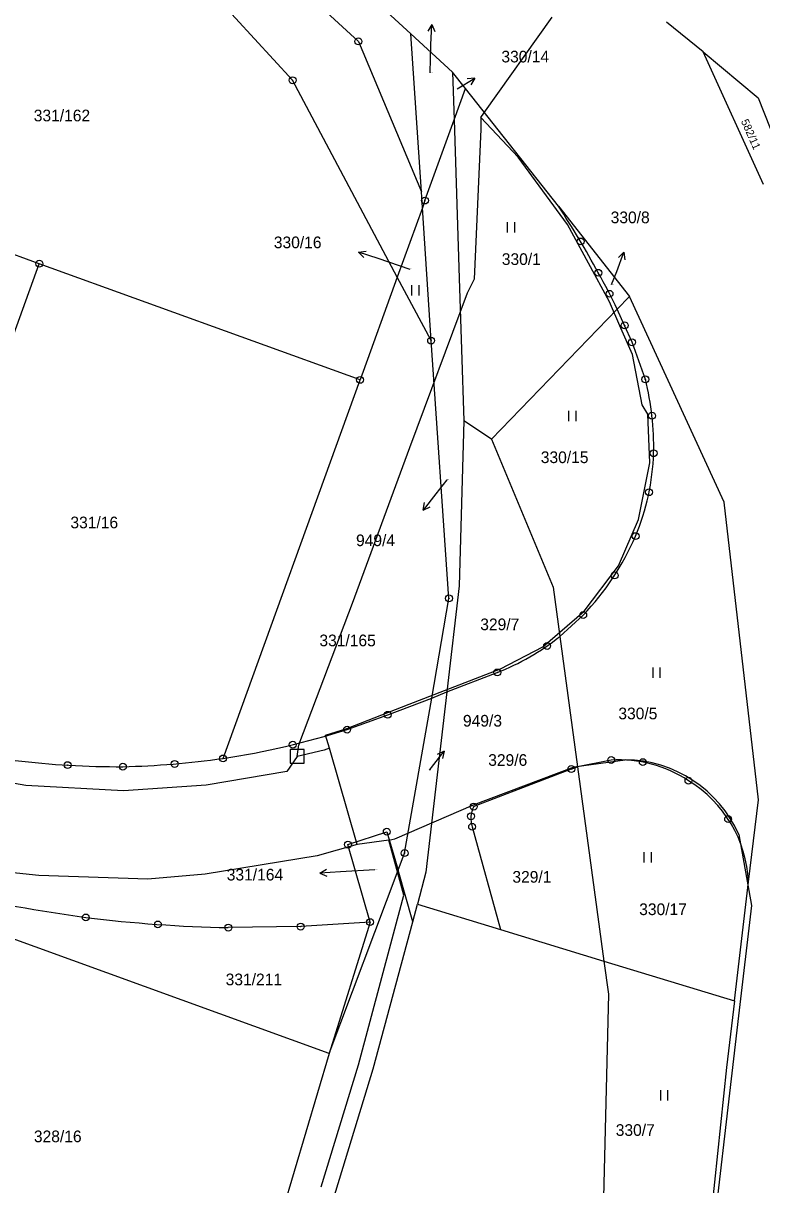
# Model space of a CAD drawing. Extents: x -770973 to -770265, y -1049936 to -1049427.
# Drawn here: x -770575 to -770521.2, y -1049731.9 to -1049647.3 of the extents above; entities that cross this region are included whole.
import ezdxf

# ---------------------------------------------------------------- set-up
doc = ezdxf.new("R2010")
doc.units = 0
for name, color, linetype in [('Vrstva 1', 7, 'Continuous'), ('Vrstva 13', 7, 'Continuous'), ('Vrstva 14', 7, 'Continuous'), ('Vrstva 16', 7, 'Continuous'), ('Vrstva 23', 7, 'Continuous'), ('Vrstva 28', 7, 'Continuous'), ('Vrstva 50', 7, 'Continuous')]:
    doc.layers.add(name, color=color, linetype=linetype)

msp = doc.modelspace()

# ---------------------------------------------------------------- linework, layer by layer
at = {"layer": 'Vrstva 1'}
for p, q in [((-770546.73, -1049648.09), (-770562.36, -1049633.74)), ((-770564.3, -1049636.03), (-770550.56, -1049648.64)), ((-770555.35, -1049651.47), (-770568.56, -1049637.05)), ((-770525.45, -1049649.4), (-770528.12, -1049647.23)), ((-770550.56, -1049648.64), (-770545.97, -1049659.6)), ((-770545.97, -1049659.6), (-770546.73, -1049648.09)), ((-770543.7, -1049650.87), (-770546.73, -1049648.09)), ((-770521.04, -1049659.06), (-770525.45, -1049649.4)), ((-770525.45, -1049649.4), (-770521.43, -1049652.75)), ((-770543.7, -1049650.87), (-770543.59, -1049654.36)), ((-770542.75, -1049652.07), (-770543.7, -1049650.87)), ((-770547.73, -1049665.8), (-770555.35, -1049651.47)), ((-770543.59, -1049654.36), (-770542.75, -1049652.07)), ((-770535.99, -1049660.64), (-770542.75, -1049652.07)), ((-770521.43, -1049652.75), (-770517.95, -1049661.6)), ((-770545.71, -1049660.23), (-770543.59, -1049654.36)), ((-770543.59, -1049654.36), (-770543.21, -1049665.87)), ((-770545.9, -1049660.75), (-770545.97, -1049659.6)), ((-770573.81, -1049664.83), (-770587.12, -1049660.01)), ((-770545.71, -1049660.23), (-770545.9, -1049660.75)), ((-770535.99, -1049660.64), (-770530.8, -1049667.22)), ((-770545.9, -1049660.75), (-770547.73, -1049665.8)), ((-770545.26, -1049670.43), (-770545.9, -1049660.75)), ((-770585.68, -1049697.62), (-770573.81, -1049664.83)), ((-770550.44, -1049673.29), (-770573.81, -1049664.83)), ((-770547.73, -1049665.8), (-770550.44, -1049673.29)), ((-770545.26, -1049670.43), (-770547.73, -1049665.8)), ((-770543.21, -1049665.87), (-770542.87, -1049676.27)), ((-770530.8, -1049667.22), (-770531.7, -1049668.15)), ((-770523.91, -1049682.19), (-770530.8, -1049667.22)), ((-770531.7, -1049668.15), (-770540.87, -1049677.61)), ((-770531.16, -1049669.32), (-770531.7, -1049668.15)), ((-770530.62, -1049670.55), (-770531.16, -1049669.32)), ((-770543.96, -1049689.2), (-770545.26, -1049670.43)), ((-770529.65, -1049673.25), (-770530.62, -1049670.55)), ((-770560.42, -1049700.86), (-770550.44, -1049673.29)), ((-770542.87, -1049676.27), (-770543.21, -1049688.3)), ((-770540.87, -1049677.61), (-770542.87, -1049676.27)), ((-770540.87, -1049677.61), (-770536.38, -1049688.39)), ((-770521.42, -1049703.88), (-770523.91, -1049682.19)), ((-770543.21, -1049688.3), (-770544.11, -1049696.02)), ((-770536.38, -1049688.39), (-770535.89, -1049691.98)), ((-770545.22, -1049696.46), (-770543.96, -1049689.2)), ((-770534.18, -1049690.42), (-770535.89, -1049691.98)), ((-770535.89, -1049691.98), (-770534.6, -1049701.47)), ((-770544.11, -1049696.02), (-770540.44, -1049694.6)), ((-770544.11, -1049696.02), (-770545.64, -1049709.14)), ((-770545.22, -1049696.46), (-770544.11, -1049696.02)), ((-770548.42, -1049697.68), (-770545.22, -1049696.46)), ((-770547.19, -1049707.75), (-770545.22, -1049696.46)), ((-770551.38, -1049698.76), (-770548.42, -1049697.68)), ((-770532.14, -1049700.98), (-770534.6, -1049701.47)), ((-770535.05, -1049701.63), (-770542.16, -1049704.37)), ((-770535.05, -1049701.63), (-770534.6, -1049701.47)), ((-770534.6, -1049701.47), (-770532.67, -1049715.62)), ((-770522.13, -1049709.84), (-770521.42, -1049703.88)), ((-770551.32, -1049707.14), (-770548.49, -1049706.2)), ((-770548.49, -1049706.2), (-770547.66, -1049709)), ((-770542.27, -1049705.84), (-770540.21, -1049713.32)), ((-770549.71, -1049712.78), (-770551.32, -1049707.14)), ((-770547.66, -1049709), (-770547.19, -1049707.75)), ((-770552.69, -1049722.34), (-770547.66, -1049709)), ((-770546.6, -1049712.76), (-770547.66, -1049709)), ((-770545.64, -1049709.14), (-770546.25, -1049711.47)), ((-770523.16, -1049718.52), (-770522.13, -1049709.84)), ((-770552.69, -1049722.34), (-770583.79, -1049711.08)), ((-770546.6, -1049712.76), (-770546.25, -1049711.47)), ((-770546.25, -1049711.47), (-770540.21, -1049713.32)), ((-770554.76, -1049713.11), (-770560.04, -1049713.18)), ((-770549.71, -1049712.78), (-770554.76, -1049713.11)), ((-770549.71, -1049712.78), (-770552.69, -1049722.34)), ((-770549.48, -1049723.46), (-770546.6, -1049712.76)), ((-770540.21, -1049713.32), (-770532.67, -1049715.62)), ((-770532.67, -1049715.62), (-770532.33, -1049718.02)), ((-770532.67, -1049715.62), (-770523.16, -1049718.52)), ((-770532.33, -1049718.02), (-770532.95, -1049742.96)), ((-770523.16, -1049718.52), (-770523.73, -1049723.36)), ((-770552.69, -1049722.34), (-770559.02, -1049743.61)), ((-770556.01, -1049744.77), (-770549.48, -1049723.46)), ((-770523.73, -1049723.36), (-770525, -1049735.43))]:
    msp.add_line(p, q, dxfattribs=at)
for centre, radius, start, end in [((-770585.493, -1049693.64), 59.494, 28.23919, 33.68832), ((-770574.083, -1049688.45), 46.994, 25.59304, 29.24725), ((-770549.116, -1049678.144), 20.072, 358.61365, 14.11348), ((-770546.161, -1049678.081), 17.12, 337.36347, 358.16211), ((-770548.173, -1049676.98), 19.402, 316.15437, 336.64965), ((-770546.558, -1049678.714), 17.023, 291.06318, 308.80557), ((-770569.584, -1049640.903), 60.653, 278.69011, 287.46571), ((-770568.043, -1049639.768), 61.693, 262.99237, 270.30037), ((-770569.078, -1049640.229), 61.246, 271.27053, 278.12682), ((-770531.588, -1049710.224), 9.26, 56.74475, 93.41775), ((-770531.296, -1049710.312), 9.179, 2.94609, 58.56839), ((-770540.45, -1049705.237), 1.917, 153.10848, 198.33259), ((-770552.252, -1049582.755), 130.951, 257.55595, 262.02506), ((-770558.126, -1049613.159), 100.039, 262.94086, 268.9036)]:
    msp.add_arc(centre, radius, start, end, dxfattribs=at)
at = {"layer": 'Vrstva 13'}
for p, q in [((-770545.33, -1049650.93), (-770545.27, -1049648.9)), ((-770546.78, -1049665.24), (-770549.13, -1049664.46)), ((-770532.11, -1049666.35), (-770531.74, -1049665.39)), ((-770544.11, -1049680.57), (-770544.92, -1049681.6)), ((-770545.39, -1049701.72), (-770545.23, -1049701.51)), ((-770549.36, -1049708.97), (-770551.87, -1049709.12))]:
    msp.add_line(p, q, dxfattribs=at)
at = {"layer": 'Vrstva 16'}
for p, q in [((-770545.22, -1049647.4), (-770545.49, -1049647.89)), ((-770545.27, -1049648.9), (-770545.22, -1049647.4)), ((-770545.22, -1049647.4), (-770544.99, -1049647.91)), ((-770543.36, -1049652.09), (-770542.07, -1049651.32)), ((-770542.07, -1049651.32), (-770542.63, -1049651.36)), ((-770542.07, -1049651.32), (-770542.37, -1049651.79)), ((-770550.55, -1049663.99), (-770550, -1049663.91)), ((-770549.13, -1049664.46), (-770550.55, -1049663.99)), ((-770550.55, -1049663.99), (-770550.16, -1049664.38)), ((-770531.74, -1049665.39), (-770531.21, -1049663.99)), ((-770531.21, -1049663.99), (-770531.62, -1049664.37)), ((-770531.21, -1049663.99), (-770531.15, -1049664.54)), ((-770544.92, -1049681.6), (-770545.85, -1049682.78)), ((-770545.85, -1049682.78), (-770545.74, -1049682.23)), ((-770545.85, -1049682.78), (-770545.34, -1049682.54)), ((-770545.23, -1049701.51), (-770544.31, -1049700.32)), ((-770544.31, -1049700.32), (-770544.82, -1049700.57)), ((-770544.31, -1049700.32), (-770544.42, -1049700.87)), ((-770553.37, -1049709.21), (-770552.88, -1049708.93)), ((-770551.87, -1049709.12), (-770553.37, -1049709.21)), ((-770553.37, -1049709.21), (-770552.85, -1049709.43))]:
    msp.add_line(p, q, dxfattribs=at)
at = {"layer": 'Vrstva 23'}
for p, q in [((-770539.69, -1049662.56), (-770539.69, -1049661.81)), ((-770539.19, -1049661.81), (-770539.19, -1049662.56)), ((-770546.66, -1049667.14), (-770546.66, -1049666.39)), ((-770546.16, -1049666.39), (-770546.16, -1049667.14)), ((-770535.22, -1049676.3), (-770535.22, -1049675.55)), ((-770534.72, -1049675.55), (-770534.72, -1049676.3)), ((-770529.09, -1049694.99), (-770529.09, -1049694.24)), ((-770528.59, -1049694.24), (-770528.59, -1049694.99)), ((-770529.73, -1049708.44), (-770529.73, -1049707.69)), ((-770529.23, -1049707.69), (-770529.23, -1049708.44)), ((-770528.53, -1049725.77), (-770528.53, -1049725.02)), ((-770528.03, -1049725.02), (-770528.03, -1049725.77))]:
    msp.add_line(p, q, dxfattribs=at)
at = {"layer": 'Vrstva 28'}
for centre, radius in [((-770550.56, -1049648.64), 0.25), ((-770550.56, -1049648.64), 0.005), ((-770555.35, -1049651.47), 0.25), ((-770555.35, -1049651.47), 0.005), ((-770545.71, -1049660.23), 0.25), ((-770545.71, -1049660.23), 0.005), ((-770534.37, -1049663.21), 0.25), ((-770534.37, -1049663.21), 0.005), ((-770573.81, -1049664.83), 0.25), ((-770573.81, -1049664.83), 0.005), ((-770533.08, -1049665.49), 0.25), ((-770533.08, -1049665.49), 0.005), ((-770532.26, -1049667.02), 0.25), ((-770532.26, -1049667.02), 0.005), ((-770531.16, -1049669.32), 0.25), ((-770531.16, -1049669.32), 0.005), ((-770545.26, -1049670.43), 0.25), ((-770545.26, -1049670.43), 0.005), ((-770530.62, -1049670.55), 0.25), ((-770530.62, -1049670.55), 0.005), ((-770550.44, -1049673.29), 0.25), ((-770550.44, -1049673.29), 0.005), ((-770529.65, -1049673.25), 0.25), ((-770529.65, -1049673.25), 0.005), ((-770529.17, -1049675.9), 0.25), ((-770529.17, -1049675.9), 0.005), ((-770529.05, -1049678.63), 0.25), ((-770529.05, -1049678.63), 0.005), ((-770529.38, -1049681.47), 0.25), ((-770529.38, -1049681.47), 0.005), ((-770530.36, -1049684.67), 0.25), ((-770530.36, -1049684.67), 0.005), ((-770531.89, -1049687.53), 0.25), ((-770531.89, -1049687.53), 0.005), ((-770543.96, -1049689.2), 0.25), ((-770543.96, -1049689.2), 0.005), ((-770534.18, -1049690.42), 0.25), ((-770534.18, -1049690.42), 0.005), ((-770536.81, -1049692.67), 0.25), ((-770536.81, -1049692.67), 0.005), ((-770540.44, -1049694.6), 0.25), ((-770540.44, -1049694.6), 0.005), ((-770548.42, -1049697.68), 0.25), ((-770548.42, -1049697.68), 0.005), ((-770551.38, -1049698.76), 0.25), ((-770551.38, -1049698.76), 0.005), ((-770555.34, -1049699.86), 0.25), ((-770555.34, -1049699.86), 0.005), ((-770571.74, -1049701.35), 0.25), ((-770567.72, -1049701.46), 0.25), ((-770563.95, -1049701.26), 0.25), ((-770563.95, -1049701.26), 0.005), ((-770560.42, -1049700.86), 0.25), ((-770560.42, -1049700.86), 0.005), ((-770532.14, -1049700.98), 0.25), ((-770532.14, -1049700.98), 0.005), ((-770529.84, -1049701.13), 0.25), ((-770529.84, -1049701.13), 0.005), ((-770571.74, -1049701.35), 0.005), ((-770567.72, -1049701.46), 0.005), ((-770535.05, -1049701.63), 0.25), ((-770535.05, -1049701.63), 0.005), ((-770526.51, -1049702.48), 0.25), ((-770526.51, -1049702.48), 0.005), ((-770542.16, -1049704.37), 0.25), ((-770542.16, -1049704.37), 0.005), ((-770542.36, -1049705.07), 0.25), ((-770542.36, -1049705.07), 0.005), ((-770523.62, -1049705.28), 0.25), ((-770523.62, -1049705.28), 0.005), ((-770548.49, -1049706.2), 0.25), ((-770548.49, -1049706.2), 0.005), ((-770542.27, -1049705.84), 0.25), ((-770542.27, -1049705.84), 0.005), ((-770551.32, -1049707.14), 0.25), ((-770551.32, -1049707.14), 0.005), ((-770547.19, -1049707.75), 0.25), ((-770547.19, -1049707.75), 0.005), ((-770570.42, -1049712.44), 0.25), ((-770570.42, -1049712.44), 0.005), ((-770565.17, -1049712.95), 0.25), ((-770565.17, -1049712.95), 0.005), ((-770560.04, -1049713.18), 0.25), ((-770554.76, -1049713.11), 0.25), ((-770554.76, -1049713.11), 0.005), ((-770549.71, -1049712.78), 0.25), ((-770549.71, -1049712.78), 0.005), ((-770560.04, -1049713.18), 0.005)]:
    msp.add_circle(centre, radius, dxfattribs=at)
at = {"layer": 'Vrstva 50'}
for p, q in [((-770541.42, -1049653.87), (-770536.43, -1049646.88)), ((-770541.64, -1049654.17), (-770541.42, -1049653.87)), ((-770541.64, -1049654.17), (-770541.65, -1049655.02)), ((-770538.91, -1049657.08), (-770541.64, -1049654.17)), ((-770541.65, -1049655.02), (-770542.12, -1049665.95)), ((-770535.32, -1049661.98), (-770538.91, -1049657.08)), ((-770532.27, -1049667.61), (-770535.32, -1049661.98)), ((-770542.12, -1049665.95), (-770542.64, -1049666.97)), ((-770542.64, -1049666.97), (-770546.84, -1049678.24)), ((-770531.44, -1049669.52), (-770532.27, -1049667.61)), ((-770530.59, -1049671.43), (-770531.44, -1049669.52)), ((-770529.88, -1049675.1), (-770530.59, -1049671.43)), ((-770529.48, -1049675.79), (-770529.88, -1049675.1)), ((-770529.32, -1049679.34), (-770529.48, -1049675.79)), ((-770546.84, -1049678.24), (-770551.01, -1049689.57)), ((-770530.15, -1049683.45), (-770529.32, -1049679.34)), ((-770531.61, -1049686.84), (-770530.15, -1049683.45)), ((-770534.12, -1049690.14), (-770531.61, -1049686.84)), ((-770551.01, -1049689.57), (-770554.86, -1049699.7)), ((-770537.13, -1049692.72), (-770534.12, -1049690.14)), ((-770540.2, -1049694.34), (-770537.13, -1049692.72)), ((-770546.85, -1049696.91), (-770540.2, -1049694.34)), ((-770551.41, -1049698.67), (-770546.85, -1049696.91)), ((-770552.95, -1049699.17), (-770551.41, -1049698.67)), ((-770552.67, -1049700.12), (-770552.95, -1049699.17)), ((-770554.52, -1049700.21), (-770555.52, -1049700.21)), ((-770555.52, -1049700.21), (-770555.52, -1049701.21)), ((-770555.02, -1049700.71), (-770554.89, -1049699.86)), ((-770553.06, -1049700.26), (-770555.02, -1049700.71)), ((-770554.86, -1049699.7), (-770554.89, -1049699.86)), ((-770554.52, -1049701.21), (-770554.52, -1049700.21)), ((-770552.67, -1049700.12), (-770553.06, -1049700.26)), ((-770550.64, -1049707.13), (-770552.67, -1049700.12)), ((-770555.02, -1049700.71), (-770555.76, -1049701.81)), ((-770555.52, -1049701.21), (-770554.52, -1049701.21)), ((-770534.85, -1049701.46), (-770531.12, -1049700.95)), ((-770574.78, -1049702.84), (-770581.57, -1049701.66)), ((-770555.77, -1049701.81), (-770561.64, -1049702.81)), ((-770542.17, -1049704.25), (-770534.85, -1049701.46)), ((-770567.66, -1049703.23), (-770574.78, -1049702.84)), ((-770561.64, -1049702.81), (-770567.66, -1049703.23)), ((-770547.91, -1049706.72), (-770542.17, -1049704.25)), ((-770550.64, -1049707.13), (-770553.57, -1049707.96)), ((-770548.35, -1049706.81), (-770550.64, -1049707.13)), ((-770548.35, -1049706.81), (-770547.91, -1049706.72)), ((-770547.24, -1049710.81), (-770548.35, -1049706.81)), ((-770522.84, -1049706.4), (-770521.92, -1049711.56)), ((-770553.57, -1049707.96), (-770561.72, -1049709.28)), ((-770573.85, -1049709.39), (-770578.34, -1049708.92)), ((-770565.9, -1049709.66), (-770573.85, -1049709.39)), ((-770561.72, -1049709.28), (-770565.9, -1049709.66)), ((-770550.55, -1049723.17), (-770547.24, -1049710.81)), ((-770521.92, -1049711.56), (-770522.87, -1049719.6)), ((-770522.87, -1049719.6), (-770523.88, -1049728.37)), ((-770553.27, -1049732.05), (-770550.55, -1049723.17)), ((-770523.88, -1049728.37), (-770525.29, -1049740.56))]:
    msp.add_line(p, q, dxfattribs=at)
msp.add_arc((-770531.239, -1049710.146), 9.197, 24.03708, 89.25609, dxfattribs=at)

# ---------------------------------------------------------------- texts
at = {"layer": 'Vrstva 14'}
for s, height, p in [('949/5', 0.05, (-770545.33, -1049650.93)), ('330/14', 0.05, (-770543.36, -1049652.09)), ('331/162', 0.85, (-770574.21, -1049654.46)), ('330/1', 0.85, (-770540.11, -1049664.92)), ('330/16', 0.05, (-770546.78, -1049665.24)), ('330/8', 0.05, (-770532.11, -1049666.35)), ('330/15', 0.85, (-770537.27, -1049679.35)), ('949/4', 0.05, (-770544.11, -1049680.57)), ('331/16', 0.85, (-770571.54, -1049684.1)), ('329/7', 0.85, (-770541.68, -1049691.52)), ('331/165', 0.85, (-770553.4, -1049692.69)), ('330/5', 0.85, (-770531.62, -1049698.01)), ('329/6', 0.85, (-770541.1, -1049701.4)), ('949/3', 0.05, (-770545.39, -1049701.72)), ('331/164', 0.05, (-770549.36, -1049708.97)), ('329/1', 0.85, (-770539.34, -1049709.91)), ('330/17', 0.85, (-770530.1, -1049712.27)), ('331/211', 0.85, (-770560.23, -1049717.38)), ('330/7', 0.85, (-770531.81, -1049728.35)), ('328/16', 0.85, (-770574.2, -1049728.81))]:
    msp.add_text(s, height=height, dxfattribs=at).set_placement(p)
msp.add_text('582/11', height=0.57, rotation=293.9625, dxfattribs=at).set_placement((-770522.7, -1049654.45))
at = {"layer": 'Vrstva 16'}
for s, p in [('330/14', (-770540.14, -1049650.17)), ('330/8', (-770532.18, -1049661.88)), ('330/16', (-770556.72, -1049663.7)), ('949/4', (-770550.73, -1049685.4)), ('949/3', (-770542.94, -1049698.54)), ('331/164', (-770560.15, -1049709.75))]:
    msp.add_text(s, height=0.85, dxfattribs=at).set_placement(p)

doc.saveas('drawing.dxf')
